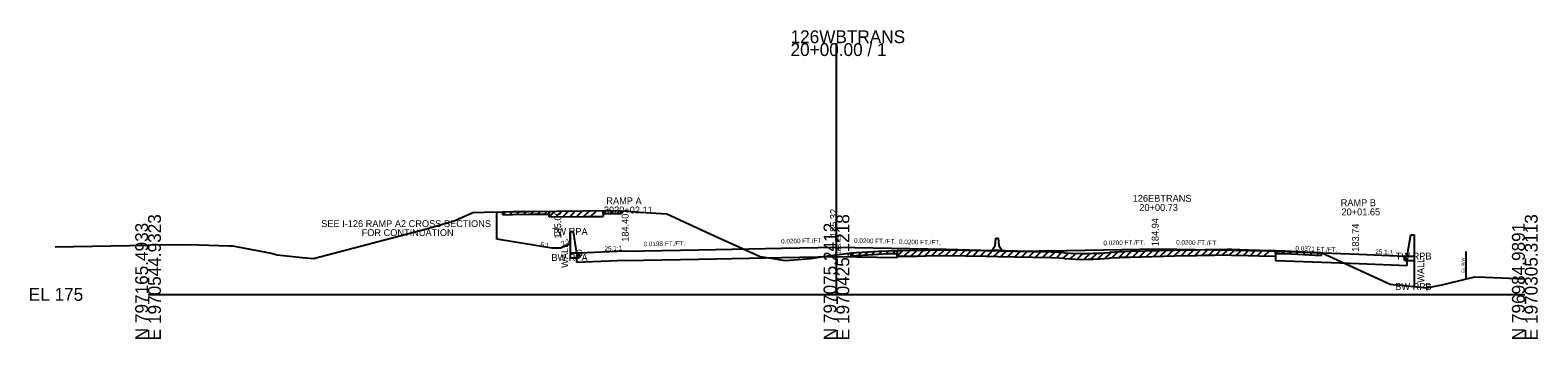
# Model space of a CAD drawing. Extents: x -6494 to 1970605, y -10 to 798140.
# Drawn here: x 974.3 to 1302.8, y 2490.3 to 2557.6 of the extents above; entities that cross this region are included whole.
import ezdxf

# ---------------------------------------------------------------- set-up
doc = ezdxf.new("R2010")
doc.units = 0
for name, color, linetype in [('Default', 7, 'Continuous'), ('RD_EX_SU_Misc_TxCode', 7, 'Continuous'), ('RD_GPK_XS_Cell', 7, 'Continuous'), ('RD_Sketch1', 7, 'Continuous'), ('RD_XS_Base', 7, 'Continuous'), ('RD_XS_Box', 7, 'Continuous'), ('RD_XS_EwShp', 7, 'Continuous'), ('RD_XS_ExGround', 7, 'Continuous'), ('RD_XS_ExPaveRet', 7, 'Continuous'), ('RD_XS_ExRW', 7, 'Continuous'), ('RD_XS_MedBWall', 7, 'Continuous'), ('RD_XS_Misc_Line', 7, 'Continuous'), ('RD_XS_Pave', 7, 'Continuous'), ('RD_XS_PaveOvlay', 7, 'Continuous'), ('RD_XS_PaveShd', 7, 'Continuous'), ('RD_XS_TieSlope', 7, 'Continuous'), ('RD_XS_TX_Elev_EX', 7, 'Continuous'), ('RD_XS_TX_Elev_PR', 7, 'Continuous'), ('RD_XS_TX_Misc', 7, 'Continuous'), ('RD_XS_TX_Notes', 7, 'Continuous'), ('RD_XS_TX_Profile', 7, 'Continuous'), ('RD_XS_TX_Slope', 7, 'Continuous'), ('RD_XS_TX_Station', 7, 'Continuous')]:
    doc.layers.add(name, color=color, linetype=linetype)

msp = doc.modelspace()

# ---------------------------------------------------------------- linework, layer by layer
at = {"layer": 'Default'}
for p, q in [((1184, 2509.8), (1184.58, 2510.64)), ((1184.58, 2510.64), (1184.75, 2512.22)), ((1184.75, 2512.22), (1185.25, 2512.22)), ((1185.25, 2512.22), (1185.42, 2510.64)), ((1185.42, 2510.64), (1186, 2509.8)), ((1184, 2509.55), (1184, 2509.8)), ((1186, 2509.55), (1184, 2509.55)), ((1186, 2509.8), (1186, 2509.55))]:
    msp.add_line(p, q, dxfattribs=at)
at = {"layer": 'RD_GPK_XS_Cell'}
for p, q in [((1150, 2500), (1150, 2554.76)), ((1000, 2500), (1150, 2500)), ((1150, 2500), (1300, 2500))]:
    msp.add_line(p, q, dxfattribs=at)
at = {"layer": 'RD_XS_Base'}
for p, q in [((1093.45, 2508.42), (1093.95, 2508.44)), ((1093.45, 2506.94), (1093.45, 2508.42)), ((1103.97, 2507.36), (1093.45, 2506.94)), ((1093.95, 2508.44), (1093.95, 2509)), ((1103.97, 2507.36), (1120.02, 2507.68)), ((1120.02, 2507.68), (1134.52, 2507.97)), ((1134.52, 2507.97), (1138, 2508.04)), ((1138, 2508.04), (1150, 2508.28)), ((1150, 2508.28), (1163.2, 2508.01)), ((1245.65, 2507.4), (1263.85, 2506.7)), ((1273.88, 2507.78), (1273.88, 2508.34)), ((1274.39, 2507.76), (1273.88, 2507.78)), ((1274.39, 2506.28), (1274.39, 2507.76)), ((1263.85, 2506.7), (1274.39, 2506.28))]:
    msp.add_line(p, q, dxfattribs=at)
at = {"layer": 'RD_XS_Box'}
for p, q in [((1091.95, 2511.61), (1091.95, 2509)), ((1093.95, 2509), (1091.95, 2509)), ((1273.88, 2508.34), (1275.89, 2508.34)), ((1275.89, 2508.34), (1275.89, 2501.72))]:
    msp.add_line(p, q, dxfattribs=at)
at = {"layer": 'RD_XS_ExGround'}
msp.add_line((979.75, 2510.38), (1000, 2510.76), dxfattribs=at)
msp.add_lwpolyline([(1000, 2510.76), (1000.52, 2510.77), (1008.78, 2510.87), (1017.67, 2510.62), (1018.42, 2510.6), (1019.55, 2510.37), (1026.86, 2508.97), (1028.14, 2508.59), (1033.64, 2508.02), (1036.03, 2507.79), (1060.64, 2514.29), (1066.67, 2516.02), (1070.78, 2517.82), (1073.24, 2517.89), (1077.3, 2517.99), (1079.45, 2518.04), (1082.96, 2518.09), (1094.84, 2518.22), (1099.93, 2518.25), (1100.85, 2518.25), (1103.19, 2518.22), (1107.25, 2517.95), (1113.02, 2517.56), (1123.4, 2512.79), (1133.38, 2508.23), (1135.81, 2507.87), (1138.85, 2507.4), (1144.4, 2507.81), (1148.12, 2508.43), (1150, 2508.65), (1153.2, 2509.03), (1159.2, 2509.39), (1161.43, 2509.53), (1167.58, 2509.61), (1169.55, 2509.63), (1173.24, 2509.72), (1173.55, 2509.73), (1174.14, 2509.72), (1178.12, 2509.66), (1182.6, 2509.58), (1185.22, 2509.53), (1188.77, 2509.45), (1196.75, 2509.28), (1198.43, 2509.21), (1199.47, 2509.16), (1199.78, 2509.04), (1201.02, 2509), (1203.21, 2508.88), (1204.93, 2508.92), (1205.93, 2508.96), (1207.38, 2509.02), (1209.42, 2509.13), (1209.7, 2509.23), (1211.72, 2509.32), (1212.1, 2509.34), (1214, 2509.39), (1223.67, 2509.64), (1228.45, 2509.74), (1230.34, 2509.78), (1232.49, 2509.82), (1235.12, 2509.86), (1236.08, 2509.83), (1239.81, 2509.72), (1242.14, 2509.66), (1247.7, 2509.51), (1250.49, 2509.37), (1255.65, 2509.11), (1267.99, 2503.44), (1270.66, 2502.23), (1271.29, 2502.17), (1272.35, 2502.06), (1278.64, 2501.45), (1282.25, 2502.19), (1287.28, 2503.4), (1289.09, 2503.82), (1291.39, 2503.72), (1300, 2503.39)], dxfattribs=at)
at = {"layer": 'RD_XS_ExPaveRet'}
for p, q in [((1077.3, 2517.37), (1077.3, 2517.99)), ((1077.3, 2517.37), (1079.45, 2517.42)), ((1079.45, 2517.42), (1082.96, 2517.46)), ((1082.96, 2517.46), (1087.37, 2517.51)), ((1087.37, 2516.89), (1087.37, 2518.14)), ((1087.37, 2518.14), (1087.37, 2517.51)), ((1087.37, 2516.89), (1094.84, 2516.97)), ((1094.84, 2516.97), (1099.17, 2517)), ((1099.17, 2518.25), (1099.17, 2517)), ((1099.17, 2517.62), (1099.17, 2518.25)), ((1099.17, 2517.62), (1099.93, 2517.63)), ((1099.93, 2517.63), (1100.85, 2517.62)), ((1100.85, 2517.62), (1103.19, 2517.6)), ((1103.19, 2518.22), (1103.19, 2517.6)), ((1153.2, 2508.41), (1153.2, 2509.03)), ((1153.2, 2508.41), (1159.2, 2508.77)), ((1159.2, 2508.77), (1161.43, 2508.9)), ((1161.43, 2508.9), (1163.2, 2508.92)), ((1163.2, 2508.3), (1163.2, 2509.55)), ((1163.2, 2509.55), (1163.2, 2508.92)), ((1163.2, 2508.3), (1167.58, 2508.36)), ((1167.58, 2508.36), (1169.55, 2508.38)), ((1169.55, 2508.38), (1173.24, 2508.47)), ((1173.24, 2508.47), (1173.55, 2508.48)), ((1173.55, 2508.48), (1174.14, 2508.47)), ((1174.14, 2508.47), (1178.12, 2508.41)), ((1178.12, 2508.41), (1182.6, 2508.33)), ((1182.6, 2508.33), (1185.22, 2508.28)), ((1185.22, 2508.28), (1188.77, 2508.2)), ((1188.77, 2508.2), (1196.75, 2508.03)), ((1196.75, 2508.03), (1198.43, 2507.96)), ((1198.43, 2507.96), (1199.47, 2507.91)), ((1199.47, 2507.91), (1199.78, 2507.79)), ((1199.78, 2507.79), (1201.02, 2507.75)), ((1201.02, 2507.75), (1203.21, 2507.63)), ((1203.21, 2507.63), (1204.93, 2507.67)), ((1204.93, 2507.67), (1205.93, 2507.71)), ((1205.93, 2507.71), (1207.38, 2507.77)), ((1207.38, 2507.77), (1209.42, 2507.88)), ((1209.42, 2507.88), (1209.7, 2507.98)), ((1209.7, 2507.98), (1211.72, 2508.07)), ((1211.72, 2508.07), (1212.1, 2508.09)), ((1212.1, 2508.09), (1214, 2508.14)), ((1214, 2508.14), (1223.67, 2508.39)), ((1223.67, 2508.39), (1228.45, 2508.49)), ((1228.45, 2508.49), (1230.34, 2508.53)), ((1230.34, 2508.53), (1232.49, 2508.57)), ((1232.49, 2508.57), (1235.12, 2508.61)), ((1235.12, 2508.61), (1236.08, 2508.58)), ((1236.08, 2508.58), (1239.81, 2508.47)), ((1239.81, 2508.47), (1242.14, 2508.41)), ((1242.14, 2508.41), (1245.65, 2508.31)), ((1245.65, 2509.56), (1245.65, 2508.31)), ((1245.65, 2508.94), (1245.65, 2509.56)), ((1245.65, 2508.94), (1247.7, 2508.88)), ((1247.7, 2508.88), (1250.49, 2508.74)), ((1250.49, 2508.74), (1255.65, 2508.48)), ((1255.65, 2509.11), (1255.65, 2508.48))]:
    msp.add_line(p, q, dxfattribs=at)
at = {"layer": 'RD_XS_ExRW'}
msp.add_line((1287.12, 2509.36), (1287.12, 2503.36), dxfattribs=at)
at = {"layer": 'RD_XS_MedBWall'}
for p, q in [((1092.7, 2513.67), (1091.95, 2513.67)), ((1091.95, 2513.67), (1091.95, 2508)), ((1091.95, 2511.56), (1091.95, 2513.67)), ((1093.45, 2509), (1092.7, 2513.67)), ((1274.38, 2508.34), (1275.13, 2513)), ((1275.13, 2513), (1275.88, 2513)), ((1275.88, 2513), (1275.88, 2507.34)), ((1091.95, 2508), (1093.95, 2508)), ((1093.95, 2509), (1093.45, 2509)), ((1093.95, 2508), (1093.95, 2509)), ((1273.88, 2507.34), (1273.88, 2508.34)), ((1273.88, 2508.34), (1274.38, 2508.34)), ((1275.88, 2507.34), (1273.88, 2507.34))]:
    msp.add_line(p, q, dxfattribs=at)
at = {"layer": 'RD_XS_Misc_Line'}
for p, q in [((1077.3, 2517.37), (1077.95, 2518.01)), ((1078.81, 2517.4), (1079.46, 2518.04)), ((1080.32, 2517.43), (1080.96, 2518.06)), ((1081.83, 2517.45), (1082.47, 2518.08)), ((1083.34, 2517.47), (1083.98, 2518.1)), ((1084.85, 2517.49), (1085.49, 2518.12)), ((1086.36, 2517.5), (1087, 2518.13)), ((1087.37, 2516.89), (1088.64, 2518.15)), ((1088.88, 2516.9), (1090.15, 2518.17)), ((1090.39, 2516.92), (1091.66, 2518.18)), ((1091.9, 2516.94), (1093.17, 2518.2)), ((1093.41, 2516.95), (1094.68, 2518.22)), ((1094.91, 2516.97), (1096.18, 2518.23)), ((1096.42, 2516.98), (1097.69, 2518.24)), ((1099.17, 2517.62), (1099.81, 2518.25)), ((1100.68, 2517.62), (1101.31, 2518.24)), ((1102.19, 2517.61), (1102.81, 2518.23)), ((1153.2, 2508.41), (1153.87, 2509.07)), ((1154.71, 2508.5), (1155.38, 2509.16)), ((1156.22, 2508.59), (1156.89, 2509.25)), ((1157.73, 2508.68), (1158.4, 2509.35)), ((1159.24, 2508.77), (1159.91, 2509.44)), ((1160.75, 2508.86), (1161.42, 2509.53)), ((1162.26, 2508.91), (1162.89, 2509.55)), ((1163.2, 2508.3), (1164.47, 2509.57)), ((1164.71, 2508.32), (1165.98, 2509.59)), ((1166.22, 2508.34), (1167.49, 2509.6)), ((1167.73, 2508.36), (1169, 2509.62)), ((1169.24, 2508.38), (1170.52, 2509.66)), ((1170.75, 2508.41), (1172.04, 2509.69)), ((1172.26, 2508.45), (1173.55, 2509.73)), ((1173.77, 2508.48), (1175.01, 2509.71)), ((1175.28, 2508.45), (1176.52, 2509.68)), ((1176.79, 2508.43), (1178.03, 2509.66)), ((1178.3, 2508.41), (1179.53, 2509.63)), ((1179.81, 2508.38), (1181.04, 2509.61)), ((1181.32, 2508.35), (1182.55, 2509.58)), ((1182.83, 2508.33), (1184.06, 2509.55)), ((1184.33, 2508.3), (1185.57, 2509.53)), ((1185.84, 2508.27), (1187.07, 2509.49)), ((1187.35, 2508.24), (1188.58, 2509.46)), ((1188.86, 2508.2), (1190.1, 2509.42)), ((1190.37, 2508.17), (1191.6, 2509.39)), ((1191.88, 2508.14), (1193.11, 2509.36)), ((1193.39, 2508.1), (1194.62, 2509.33)), ((1194.9, 2508.07), (1196.13, 2509.3)), ((1196.41, 2508.04), (1197.62, 2509.24)), ((1197.92, 2507.98), (1199.12, 2509.17)), ((1199.43, 2507.91), (1200.54, 2509.01)), ((1200.94, 2507.75), (1202.14, 2508.94)), ((1202.45, 2507.67), (1203.68, 2508.89)), ((1203.96, 2507.65), (1205.26, 2508.94)), ((1205.47, 2507.69), (1206.78, 2508.99)), ((1206.98, 2507.75), (1208.3, 2509.07)), ((1208.49, 2507.83), (1209.91, 2509.24)), ((1210, 2508), (1211.32, 2509.3)), ((1211.51, 2508.06), (1212.81, 2509.36)), ((1213.02, 2508.11), (1214.31, 2509.4)), ((1214.53, 2508.15), (1215.82, 2509.44)), ((1216.04, 2508.19), (1217.33, 2509.48)), ((1217.55, 2508.23), (1218.84, 2509.52)), ((1219.06, 2508.27), (1220.35, 2509.56)), ((1220.57, 2508.31), (1221.86, 2509.6)), ((1222.08, 2508.35), (1223.37, 2509.64)), ((1223.58, 2508.39), (1224.87, 2509.67)), ((1225.09, 2508.42), (1226.38, 2509.7)), ((1226.6, 2508.45), (1227.89, 2509.73)), ((1228.11, 2508.48), (1229.4, 2509.76)), ((1229.62, 2508.51), (1230.91, 2509.79)), ((1231.13, 2508.54), (1232.41, 2509.81)), ((1232.64, 2508.57), (1233.92, 2509.84)), ((1234.15, 2508.59), (1235.42, 2509.85)), ((1235.66, 2508.6), (1236.88, 2509.81)), ((1237.17, 2508.55), (1238.39, 2509.77)), ((1238.68, 2508.51), (1239.9, 2509.72)), ((1240.19, 2508.46), (1241.42, 2509.68)), ((1241.7, 2508.42), (1242.92, 2509.64)), ((1243.21, 2508.38), (1244.43, 2509.6)), ((1245.65, 2508.94), (1246.26, 2509.55)), ((1247.16, 2508.9), (1247.77, 2509.5)), ((1248.67, 2508.83), (1249.27, 2509.43)), ((1250.18, 2508.76), (1250.78, 2509.35)), ((1251.69, 2508.68), (1252.29, 2509.28)), ((1253.2, 2508.61), (1253.8, 2509.2)), ((1254.71, 2508.53), (1255.31, 2509.13))]:
    msp.add_line(p, q, dxfattribs=at)
at = {"layer": 'RD_XS_Pave'}
for p, q in [((1134.52, 2510.01), (1138, 2510.08)), ((1138, 2510.08), (1150, 2510.32)), ((1150, 2510.32), (1174, 2509.84)), ((1103.97, 2509.4), (1120.02, 2509.72)), ((1196.2, 2509.46), (1220.2, 2509.94)), ((1220.2, 2509.94), (1232.2, 2509.7)), ((1232.2, 2509.7), (1244.2, 2509.46)), ((1244.2, 2509.46), (1263.85, 2508.74))]:
    msp.add_line(p, q, dxfattribs=at)
at = {"layer": 'RD_XS_PaveOvlay'}
for p, q in [((1163.2, 2509.55), (1167.58, 2509.61)), ((1163.2, 2509.55), (1163.2, 2508.01)), ((1167.58, 2509.61), (1169.55, 2509.63)), ((1169.55, 2509.63), (1173.24, 2509.72)), ((1173.24, 2509.72), (1173.55, 2509.73)), ((1173.55, 2509.73), (1174.14, 2509.72)), ((1174.14, 2509.72), (1178.12, 2509.66)), ((1178.12, 2509.66), (1182.6, 2509.58)), ((1182.6, 2509.58), (1185.22, 2509.53)), ((1185.22, 2509.53), (1188.77, 2509.45)), ((1188.77, 2509.45), (1196.75, 2509.28)), ((1196.75, 2509.28), (1198.43, 2509.21)), ((1198.43, 2509.21), (1199.47, 2509.16)), ((1199.47, 2509.16), (1199.78, 2509.04)), ((1199.78, 2509.04), (1201.02, 2509)), ((1201.02, 2509), (1203.21, 2508.88)), ((1203.21, 2508.88), (1204.93, 2508.92)), ((1204.93, 2508.92), (1205.93, 2508.96)), ((1205.93, 2508.96), (1207.38, 2509.02)), ((1207.38, 2509.02), (1209.42, 2509.13)), ((1209.42, 2509.13), (1209.7, 2509.23)), ((1209.7, 2509.23), (1211.72, 2509.32)), ((1211.72, 2509.32), (1212.1, 2509.34)), ((1212.1, 2509.34), (1214, 2509.39)), ((1214, 2509.39), (1223.67, 2509.64)), ((1223.67, 2509.64), (1228.45, 2509.74)), ((1228.45, 2509.74), (1230.34, 2509.78)), ((1230.34, 2509.78), (1232.49, 2509.82)), ((1232.49, 2509.82), (1235.12, 2509.86)), ((1235.12, 2509.86), (1236.08, 2509.83)), ((1236.08, 2509.83), (1239.81, 2509.72)), ((1239.81, 2509.72), (1242.14, 2509.66)), ((1242.14, 2509.66), (1245.65, 2509.56)), ((1245.65, 2509.56), (1245.65, 2507.4))]:
    msp.add_line(p, q, dxfattribs=at)
at = {"layer": 'RD_XS_PaveShd'}
for p, q in [((1120.02, 2509.72), (1134.52, 2510.01)), ((1103.97, 2509.4), (1093.95, 2509)), ((1174, 2509.84), (1184, 2509.55)), ((1192.1, 2509.38), (1184, 2509.55)), ((1196.2, 2509.46), (1192.1, 2509.38)), ((1263.85, 2508.74), (1273.88, 2508.34))]:
    msp.add_line(p, q, dxfattribs=at)
at = {"layer": 'RD_XS_TieSlope'}
for p, q in [((1075.99, 2512.04), (1075.99, 2517.96)), ((1087.95, 2510.05), (1075.99, 2512.04)), ((1089.95, 2510.05), (1087.95, 2510.05)), ((1091.95, 2511.05), (1089.95, 2510.05))]:
    msp.add_line(p, q, dxfattribs=at)

# ---------------------------------------------------------------- texts
at = {"layer": 'RD_EX_SU_Misc_TxCode'}
msp.add_text('G', height=1.5, dxfattribs=at).set_placement((1093.2, 2508.25))
at = {"layer": 'RD_GPK_XS_Cell'}
for s, p in [('126WBTRANS', (1140, 2554.76)), ('20+00.00 / 1', (1140, 2551.96)), ('EL 175', (974, 2498.6))]:
    msp.add_text(s, height=2.8, dxfattribs=at).set_placement(p)
for s, p in [('E 1970544.9323', (1002.8, 2490)), ('E 1970425.1218', (1152.8, 2490)), ('E 1970305.3113', (1302.8, 2490)), ('N 797165.4933', (1000, 2490)), ('N 797075.2412', (1150, 2490)), ('N 796984.9891', (1300, 2490))]:
    msp.add_text(s, height=2.8, rotation=90, dxfattribs=at).set_placement(p)
at = {"layer": 'RD_Sketch1'}
msp.add_text('T', height=1.5, dxfattribs=at).set_placement((1278.08, 2500.7))
at = {"layer": 'RD_XS_EwShp'}
for s, p in [('TW RPA', (1087.98, 2512.97)), ('BW RPA', (1087.88, 2507.3)), ('TW RPB', (1271.87, 2507.59)), ('BW RPB', (1271.76, 2500.97))]:
    msp.add_text(s, height=1.5, dxfattribs=at).set_placement(p)
at = {"layer": 'RD_XS_ExRW'}
msp.add_text('Ex. R/W ', height=0.65, rotation=90, dxfattribs=at).set_placement((1286.87, 2504.74))
at = {"layer": 'RD_XS_TX_Elev_EX'}
msp.add_text('183.65', height=1, rotation=90, dxfattribs=at).set_placement((1151, 2508.65))
at = {"layer": 'RD_XS_TX_Elev_PR'}
for s, p in [('184.40', (1104.72, 2511.47)), ('185.32', (1150.13, 2512.51)), (' 184.94', (1220.2, 2509.94)), (' 183.74', (1263.85, 2508.74))]:
    msp.add_text(s, height=1.5, rotation=90, dxfattribs=at).set_placement(p)
at = {"layer": 'RD_XS_TX_Misc'}
msp.add_text('185.00', height=1.5, rotation=90, dxfattribs=at).set_placement((1090.03, 2512.18))
at = {"layer": 'RD_XS_TX_Notes'}
for s, p in [('SEE I-126 RAMP A2 CROSS SECTIONS', (1037.72, 2514.67)), ('FOR CONTINUATION', (1046.53, 2512.71))]:
    msp.add_text(s, height=1.5, dxfattribs=at).set_placement(p)
for p in [(1091.54, 2505.79), (1278.08, 2502.54)]:
    msp.add_text('WALL', height=1.5, rotation=90, dxfattribs=at).set_placement(p)
at = {"layer": 'RD_XS_TX_Profile'}
msp.add_text('25.1:1', height=1, rotation=357.7178, dxfattribs=at).set_placement((1267.4, 2508.84))
at = {"layer": 'RD_XS_TX_Slope'}
for s, rotation, p in [('6:1', 350.5377, (1085.43, 2510.47)), ('2:1', 26.5651, (1090.35, 2510.56)), ('25.1:1', 2.2844, (1099.48, 2509.47)), ('0.0198 FT./FT.', 1.1362, (1107.98, 2510.48)), ('0.0200 FT./FT.', 1.1435, (1137.96, 2511.08)), ('0.0200 FT./FT.', 358.8542, (1153.83, 2511.24)), ('0.0200 FT./FT.', 358.8542, (1163.62, 2510.98)), ('0.0200 FT./FT.', 1.1455, (1208.18, 2510.7)), ('0.0200 FT./FT.', 358.854, (1224.02, 2510.87)), ('0.0371 FT./FT.', 357.8763, (1250, 2509.55))]:
    msp.add_text(s, height=1, rotation=rotation, dxfattribs=at).set_placement(p)
at = {"layer": 'RD_XS_TX_Station'}
for s, p in [('RAMP A', (1099.86, 2519.65)), ('126EBTRANS', (1214.55, 2520.19)), ('RAMP B', (1259.88, 2519.23)), ('3020+02.11', (1099.33, 2517.65)), ('20+00.73', (1216, 2518.19)), ('20+01.65', (1260.05, 2517.23))]:
    msp.add_text(s, height=1.5, dxfattribs=at).set_placement(p)

doc.saveas('drawing.dxf')
